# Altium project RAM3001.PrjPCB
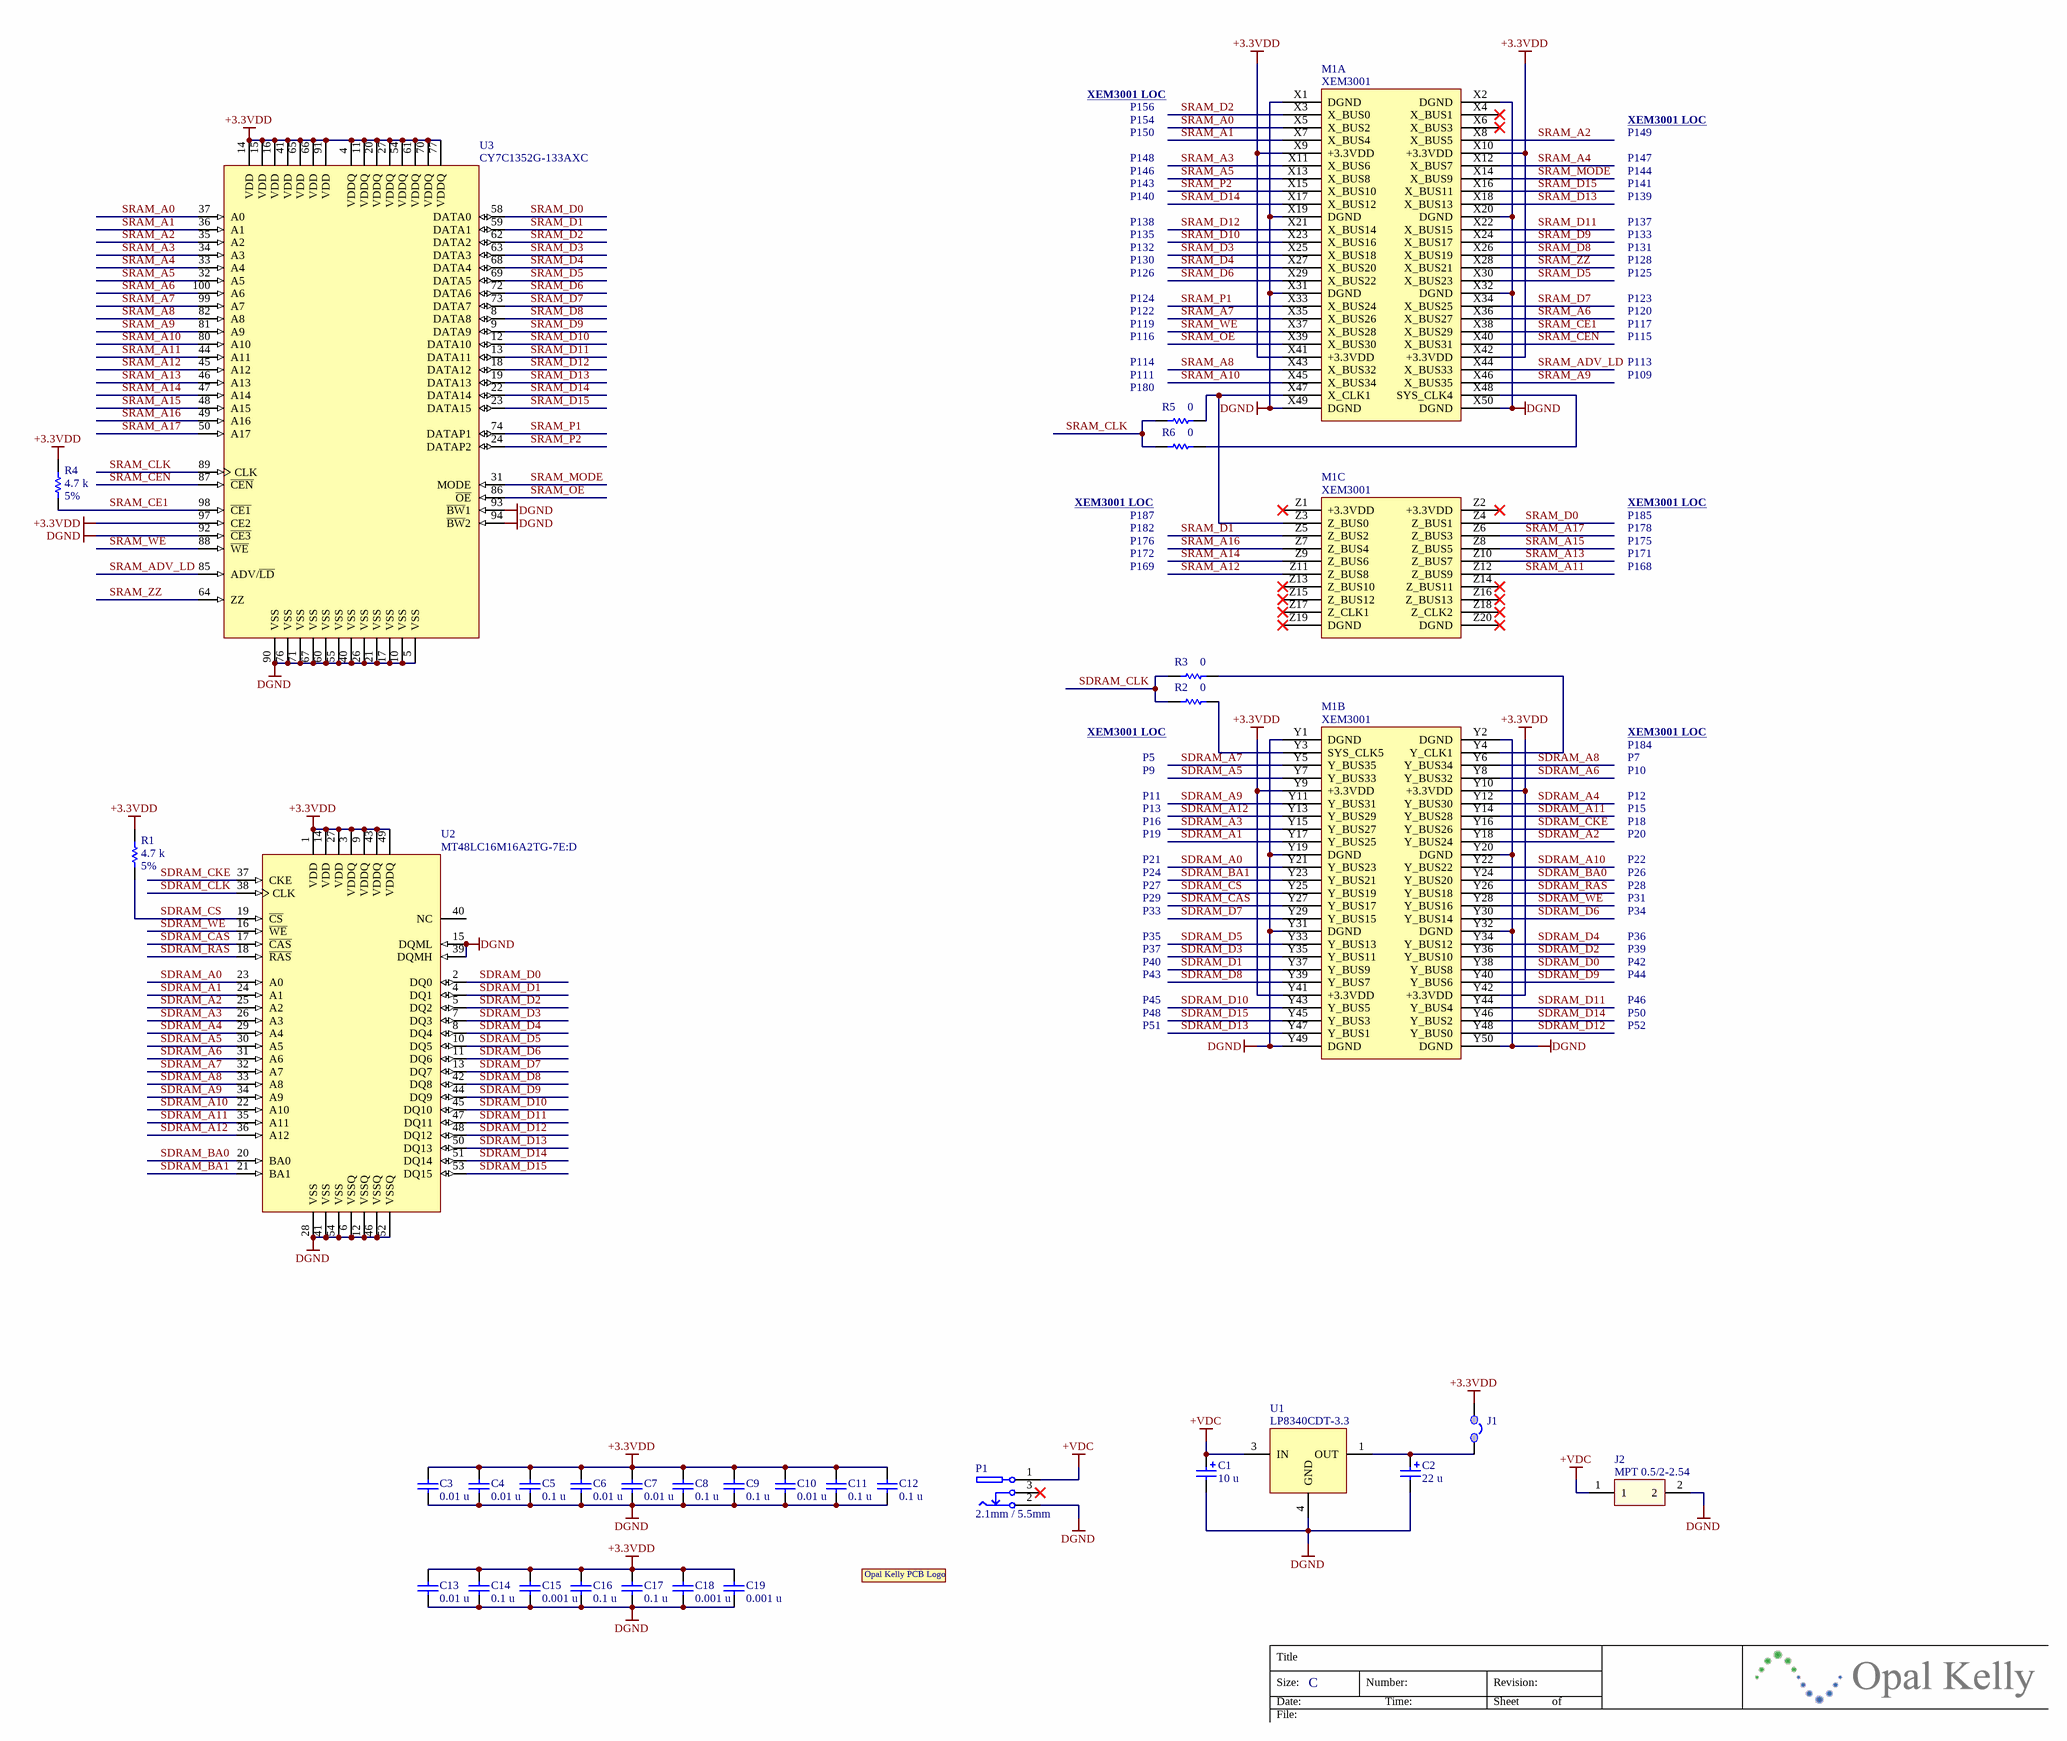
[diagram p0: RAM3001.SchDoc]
1 sheet, 33 parts. Net scope: global (net labels, ports and power ports of the same name join across sheets).
Board file: RAM3001.PcbDoc

## Sheet RAM3001.SchDoc: RAM3001
size C; Author: Garrick Kremesec; Organization: Opal Kelly; Address1: 13500 SW 72nd Ave; Address2: STE 120; Address3: Portland, OR  97223; Address4: http://www.opalkelly.com; DocumentNumber: 1; Revision: 1.2; SheetNumber: 1; SheetTotal: 1; PageSetup: Record=PageOptions|CenterHorizontal=True|CenterVertical=True|PrintScale=0.54|XCorrection=1.00|YCorrection=1.00|PrintKind=1|BorderSize=5000000|LeftOffset=0|BottomOffset=0|Orientation=2|PaperLength=1000|PaperWidth=1000|Scale=100|PaperSource=7|PrintQuality=-4|MediaType=1|DitherType=10|PaperKind=Letter|PrintScaleMode=1

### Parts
C1  value 10 u  [TC3216-1206]  (hidden comment: SM-A, 10v, 10%)
C2  value 22 u  [TC3528-1411]  (hidden comment: SM-A, 6.3v, 10%)
C3  value 0.01 u  [CC1608-0603]  (hidden comment: SM-0603, 10%, 16v)
C4  value 0.01 u  [CC1608-0603]  (hidden comment: SM-0603, 10%, 16v)
C5  value 0.1 u  [CC1608-0603]  (hidden comment: SM-0603, 10%, 16v)
C6  value 0.01 u  [CC1608-0603]  (hidden comment: SM-0603, 10%, 16v)
C7  value 0.01 u  [CC1608-0603]  (hidden comment: SM-0603, 10%, 16v)
C8  value 0.1 u  [CC1608-0603]  (hidden comment: SM-0603, 10%, 16v)
C9  value 0.1 u  [CC1608-0603]  (hidden comment: SM-0603, 10%, 16v)
C10  value 0.01 u  [CC1608-0603]  (hidden comment: SM-0603, 10%, 16v)
C11  value 0.1 u  [CC1608-0603]  (hidden comment: SM-0603, 10%, 16v)
C12  value 0.1 u  [CC1608-0603]  (hidden comment: SM-0603, 10%, 16v)
C13  value 0.01 u  [CC1608-0603]  (hidden comment: SM-0603, 10%, 16v)
C14  value 0.1 u  [CC1608-0603]  (hidden comment: SM-0603, 10%, 16v)
C15  value 0.001 u  [CC1608-0603]  (hidden comment: SM-0603, 10%, 16v)
C16  value 0.1 u  [CC1608-0603]  (hidden comment: SM-0603, 10%, 16v)
C17  value 0.1 u  [CC1608-0603]  (hidden comment: SM-0603, 10%, 16v)
C18  value 0.001 u  [CC1608-0603]  (hidden comment: SM-0603, 10%, 16v)
C19  value 0.001 u  [CC1608-0603]  (hidden comment: SM-0603, 10%, 16v)
J1  0.1" spacing  [HDR1X2]  (value not drawn)
J2  ManufacturerPartNumber: MPT 0.5/2-2.54  [MPT-0.5/2-2.54]  (hidden comment: 2.54mm, 2-position)
M1  XEM3001  [XEM3001MODULE]  (parts A,B,C of 3)
P1  2.1mm / 5.5mm  [CUI-PJ102A]
R1  value 4.7 k  Tolerance: 5%  [CR1608-0603]  (hidden comment: SM-0603, 5%, 1/10W)
R2  value 0  [CR1608-0603]  (hidden comment: SM-0603, 5%, 1/10W)
R3  value 0  [CR1608-0603]  (hidden comment: SM-0603, 5%, 1/10W)
R4  value 4.7 k  Tolerance: 5%  [CR1608-0603]  (hidden comment: SM-0603, 5%, 1/10W)
R5  value 0  [CR1608-0603]  (hidden comment: SM-0603, 5%, 1/10W)
R6  value 0  [CR1608-0603]  (hidden comment: SM-0603, 5%, 1/10W)
U1  ManufacturerPartNumber: LP8340CDT-3.3  [SIP-G3/Z11.05]  (hidden comment: 1A, 3-pin DPAK)
U2  ManufacturerPartNumber: MT48LC16M16A2TG-7E:D  [TSOP2-54]  (hidden comment: 4Mbx16x4, TSOP)
U3  ManufacturerPartNumber: CY7C1352G-133AXC  [TQFP-100]  (hidden comment: 2.5v/3.3v, 133 MHz, 256kx18)
  OKLOGO  [oklogotiny]  (value not drawn)

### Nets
+3.3VDD: C3.1 C4.1 C5.1 C6.1 C7.1 C8.1 C9.1 C10.1 C11.1 C12.1 C13.1 C14.1 C15.1 C16.1 C17.1 C18.1 C19.1 J1.1 M1.X9(+3.3VDD) M1.X10(+3.3VDD) M1.X41(+3.3VDD) M1.X42(+3.3VDD) M1.Y9(+3.3VDD) M1.Y10(+3.3VDD) M1.Y41(+3.3VDD) M1.Y42(+3.3VDD) R1.1 R4.1 U2.1(VDD) U2.3(VDDQ) U2.9(VDDQ) U2.14(VDD) U2.27(VDD) U2.43(VDDQ) U2.49(VDDQ) U3.4(VDDQ) U3.11(VDDQ) U3.14(VDD) U3.15(VDD) U3.16(VDD) U3.20(VDDQ) U3.27(VDDQ) U3.41(VDD) U3.54(VDDQ) U3.61(VDDQ) U3.65(VDD) U3.66(VDD) U3.70(VDDQ) U3.77(VDDQ) U3.91(VDD) U3.97(CE2)
+VDC: C1.1 J2.1 P1.1 U1.3(IN)
DGND: C1.2 C2.2 C3.2 C4.2 C5.2 C6.2 C7.2 C8.2 C9.2 C10.2 C11.2 C12.2 C13.2 C14.2 C15.2 C16.2 C17.2 C18.2 C19.2 J2.2 M1.X1(DGND) M1.X2(DGND) M1.X19(DGND) M1.X20(DGND) M1.X31(DGND) M1.X32(DGND) M1.X49(DGND) M1.X50(DGND) M1.Y1(DGND) M1.Y2(DGND) M1.Y19(DGND) M1.Y20(DGND) M1.Y31(DGND) M1.Y32(DGND) M1.Y49(DGND) M1.Y50(DGND) P1.2 U1.4(GND) U2.6(VSSQ) U2.12(VSSQ) U2.15(DQML) U2.28(VSS) U2.39(DQMH) U2.41(VSS) U2.46(VSSQ) U2.52(VSSQ) U2.54(VSS) U3.5(VSS) U3.10(VSS) U3.17(VSS) U3.21(VSS) U3.26(VSS) U3.40(VSS) U3.55(VSS) U3.60(VSS) U3.67(VSS) U3.71(VSS) U3.76(VSS) U3.90(VSS) U3.92(~{CE3}) U3.93(~{BW}1) U3.94(~{BW}2)
SDRAM_A0: M1.Y21(Y_BUS23) U2.23(A0)
SDRAM_A1: M1.Y17(Y_BUS25) U2.24(A1)
SDRAM_A2: M1.Y18(Y_BUS24) U2.25(A2)
SDRAM_A3: M1.Y15(Y_BUS27) U2.26(A3)
SDRAM_A4: M1.Y12(Y_BUS30) U2.29(A4)
SDRAM_A5: M1.Y7(Y_BUS33) U2.30(A5)
SDRAM_A6: M1.Y8(Y_BUS32) U2.31(A6)
SDRAM_A7: M1.Y5(Y_BUS35) U2.32(A7)
SDRAM_A8: M1.Y6(Y_BUS34) U2.33(A8)
SDRAM_A9: M1.Y11(Y_BUS31) U2.34(A9)
SDRAM_A10: M1.Y22(Y_BUS22) U2.22(A10)
SDRAM_A11: M1.Y14(Y_BUS28) U2.35(A11)
SDRAM_A12: M1.Y13(Y_BUS29) U2.36(A12)
SDRAM_BA0: M1.Y24(Y_BUS20) U2.20(BA0)
SDRAM_BA1: M1.Y23(Y_BUS21) U2.21(BA1)
SDRAM_CAS: M1.Y27(Y_BUS17) U2.17(~{CAS})
SDRAM_CKE: M1.Y16(Y_BUS26) U2.37(CKE)
SDRAM_CLK: R2.1 R3.1 U2.38(CLK)
SDRAM_CS: M1.Y25(Y_BUS19) R1.2 U2.19(~{CS})
SDRAM_D0: M1.Y38(Y_BUS8) U2.2(DQ0)
SDRAM_D1: M1.Y37(Y_BUS9) U2.4(DQ1)
SDRAM_D2: M1.Y36(Y_BUS10) U2.5(DQ2)
SDRAM_D3: M1.Y35(Y_BUS11) U2.7(DQ3)
SDRAM_D4: M1.Y34(Y_BUS12) U2.8(DQ4)
SDRAM_D5: M1.Y33(Y_BUS13) U2.10(DQ5)
SDRAM_D6: M1.Y30(Y_BUS14) U2.11(DQ6)
SDRAM_D7: M1.Y29(Y_BUS15) U2.13(DQ7)
SDRAM_D8: M1.Y39(Y_BUS7) U2.42(DQ8)
SDRAM_D9: M1.Y40(Y_BUS6) U2.44(DQ9)
SDRAM_D10: M1.Y43(Y_BUS5) U2.45(DQ10)
SDRAM_D11: M1.Y44(Y_BUS4) U2.47(DQ11)
SDRAM_D12: M1.Y48(Y_BUS0) U2.48(DQ12)
SDRAM_D13: M1.Y47(Y_BUS1) U2.50(DQ13)
SDRAM_D14: M1.Y46(Y_BUS2) U2.51(DQ14)
SDRAM_D15: M1.Y45(Y_BUS3) U2.53(DQ15)
SDRAM_RAS: M1.Y26(Y_BUS18) U2.18(~{RAS})
SDRAM_WE: M1.Y28(Y_BUS16) U2.16(~{WE})
SRAM_A0: M1.X5(X_BUS2) U3.37(A0)
SRAM_A1: M1.X7(X_BUS4) U3.36(A1)
SRAM_A2: M1.X8(X_BUS5) U3.35(A2)
SRAM_A3: M1.X11(X_BUS6) U3.34(A3)
SRAM_A4: M1.X12(X_BUS7) U3.33(A4)
SRAM_A5: M1.X13(X_BUS8) U3.32(A5)
SRAM_A6: M1.X36(X_BUS27) U3.100(A6)
SRAM_A7: M1.X35(X_BUS26) U3.99(A7)
SRAM_A8: M1.X43(X_BUS32) U3.82(A8)
SRAM_A9: M1.X46(X_BUS35) U3.81(A9)
SRAM_A10: M1.X45(X_BUS34) U3.80(A10)
SRAM_A11: M1.Z12(Z_BUS9) U3.44(A11)
SRAM_A12: M1.Z11(Z_BUS8) U3.45(A12)
SRAM_A13: M1.Z10(Z_BUS7) U3.46(A13)
SRAM_A14: M1.Z9(Z_BUS6) U3.47(A14)
SRAM_A15: M1.Z8(Z_BUS5) U3.48(A15)
SRAM_A16: M1.Z7(Z_BUS4) U3.49(A16)
SRAM_A17: M1.Z6(Z_BUS3) U3.50(A17)
SRAM_ADV_LD: M1.X44(X_BUS33) U3.85(ADV/~{LD})
SRAM_CE1: M1.X38(X_BUS29) R4.2 U3.98(~{CE1})
SRAM_CEN: M1.X40(X_BUS31) U3.87(~{CEN})
SRAM_CLK: R5.1 R6.1 U3.89(CLK)
SRAM_D0: M1.Z4(Z_BUS1) U3.58(DATA0)
SRAM_D1: M1.Z5(Z_BUS2) U3.59(DATA1)
SRAM_D2: M1.X3(X_BUS0) U3.62(DATA2)
SRAM_D3: M1.X25(X_BUS18) U3.63(DATA3)
SRAM_D4: M1.X27(X_BUS20) U3.68(DATA4)
SRAM_D5: M1.X30(X_BUS23) U3.69(DATA5)
SRAM_D6: M1.X29(X_BUS22) U3.72(DATA6)
SRAM_D7: M1.X34(X_BUS25) U3.73(DATA7)
SRAM_D8: M1.X26(X_BUS19) U3.8(DATA8)
SRAM_D9: M1.X24(X_BUS17) U3.9(DATA9)
SRAM_D10: M1.X23(X_BUS16) U3.12(DATA10)
SRAM_D11: M1.X22(X_BUS15) U3.13(DATA11)
SRAM_D12: M1.X21(X_BUS14) U3.18(DATA12)
SRAM_D13: M1.X18(X_BUS13) U3.19(DATA13)
SRAM_D14: M1.X17(X_BUS12) U3.22(DATA14)
SRAM_D15: M1.X16(X_BUS11) U3.23(DATA15)
SRAM_MODE: M1.X14(X_BUS9) U3.31(MODE)
SRAM_OE: M1.X39(X_BUS30) U3.86(~{OE})
SRAM_P1: M1.X33(X_BUS24) U3.74(DATAP1)
SRAM_P2: M1.X15(X_BUS10) U3.24(DATAP2)
SRAM_WE: M1.X37(X_BUS28) U3.88(~{WE})
SRAM_ZZ: M1.X28(X_BUS21) U3.64(ZZ)
NetC2_1: C2.1 J1.2 U1.1(OUT)
NetM1_X47: M1.X47(X_CLK1) M1.Z3(Z_BUS0) R5.2
NetM1_X48: M1.X48(SYS_CLK4) R6.2
NetM1_Y3: M1.Y3(SYS_CLK5) R2.2
NetM1_Y4: M1.Y4(Y_CLK1) R3.2

Not connected (* = marked no-connect by the designer): M1 X4(X_BUS1)* X6(X_BUS3)* Z1(+3.3VDD)* Z2(+3.3VDD)* Z13(Z_BUS10)* Z14(Z_BUS11)* Z15(Z_BUS12)* Z16(Z_BUS13)* Z17(Z_CLK1)* Z18(Z_CLK2)* Z19(DGND)* Z20(DGND)*; P1 3*; U2 40(NC)

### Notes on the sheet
- P154
- P156
- XEM3001 LOC
- P148
- P146
- P143
- P150
- P147
- P144
- P141
- P149
- P132
- P140
- P138
- P135
- P131
- P139
- P137
- P133
- P122
- P124
- P126
- P130
- P120
- P123
- P125
- P128
- P111
- P114
- P116
- P119
- P109
- P113
- P115
- P117
- (near R5) P180
- P176
- P172
- P169
- P187
- P182
- P178
- P175
- P171
- P168
- P185
- P5
- (near R2) XEM3001 LOC
- P184
- P7
- P16
- P13
- P11
- P9
- P10
- P12
- P15
- P18
- P27
- P24
- P21
- P19
- P28
- P20
- P22
- P26
- P29
- P33
- P35
- P37
- P31
- P34
- P36
- P39
- P40
- P43
- P45
- P48
- P42
- P44
- P46
- P50
- P51
- P52
- Title
- Size:
- Date:
- File:
- C
- Number:
- Time:
- Revision:
- Sheet
- of

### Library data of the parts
C1 = Capacitor Pol: Tantalum capacitor; Manufacturer: 13; PartNumber: 18; ManufacturerPartNumber: T491A106K010AS; Class I: Passive
C2 = Capacitor Pol: Tantalum capacitor; Manufacturer: 13; PartNumber: 87; ManufacturerPartNumber: T491B226K006AS; Class I: Passive
C3 C4 C6 C7 C10 C13 = Capacitor: Ceramic capacitor; Manufacturer: 14; PartNumber: 20; Class I: Passive
C5 C8 C9 C11 C12 C14 C16 C17 = Capacitor: Ceramic capacitor; Manufacturer: 14; PartNumber: 19; Class I: Passive
C15 C18 C19 = Capacitor: Ceramic capacitor; Manufacturer: 14; PartNumber: 86; Class I: Passive
J1 = Jumper 1X2: Header; Manufacturer: 11; PartNumber: 15; ManufacturerPartNumber: 4-103186-0; Class I: Connector
J2 = Terminal 1x2: Terminal block connector; PartNumber: 84; Manufacturer: 24
M1 = XEM3001: XEM3001 Module Connector; Manufacturer: Generic Components
P1 = DCPOWER: DC power connector; Manufacturer: 21; PartNumber: 38; ManufacturerPartNumber: PJ-102A
R1 R4 = Resistor: Thick-film resistor; Manufacturer: 14; PartNumber: 26; Class I: Passive
R2 R3 R5 R6 = Resistor: Thick-film resistor; Manufacturer: 14; PartNumber: 51; Class I: Passive
U1 = LP8340CDT: LDO Regulator; Manufacturer: 4; PartNumber: 83
U2 = MT48LC16M16A2TG-7E: 32MB SDRAM; PartNumber: 88; Manufacturer: 17; CycleTime: 7.5ns @ CL = 2 (PC133); RowAddress: 8K (A0-A12); ColumnAddress: 512 (A0-A8)
U3 = CY7C1352G: 4Mb Pipelined SRAM, NoBL; PartNumber: 82; Manufacturer: 2
 = OKLOGO: Opal Kelly PCB Logo; Opal Kelly: Publisher; September 2004: Date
